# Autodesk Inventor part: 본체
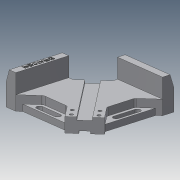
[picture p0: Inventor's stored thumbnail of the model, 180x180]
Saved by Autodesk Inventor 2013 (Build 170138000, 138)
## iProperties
Created: 2020-05
Part Number: 본체
Material: 알루미늄 6061
Document SubType Name: Modeling
Designer: user
Density: 2.71 g/cm^3
Mass: 582.584 g
Surface Area: 409.716 cm^2
Volume: 214.976 cm^3
Author: user
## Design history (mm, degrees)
sketch "스케치1"
  geometry: L1 (60, -60)-(-60, -60); L2 (-60, -60)-(-60, 60); L3 (-60, 60)-(60, 60); L4 (60, 60)-(60, -60); L5 (60, -60)-(-60, 60); L6 (-60, -60)-(60, 60); 1 further point
  constraints: 12 end point, 2 midpoint, 2 parallel, 1 horizontal, 1 perpendicular
  dimensions: "d0" = 120 distance of L2.end L3.end; "d1" = 120 distance of L1.end L2.end
extrude "돌출1" new body sketch "스케치1" distance "d2" = 18; taper "d3" = 0 deg
sketch "스케치2"
  geometry: L1 (-60, -60)-(60, -60) reference; L2 (60, -60)-(60, 60) reference; L3 (60, -60)-(80, -60); L4 (31.716, -60)-(60, -60); L5 (60, -31.716)-(60, -60); L6 (31.716, -60)-(60, -31.716); 1 further point
  constraints: 8 end point, 2 point on line, 1 collinear, 1 horizontal, 1 perpendicular
extrude "돌출2" cut sketch "스케치2" stored distance "d6" = 0; taper "d7" = 0 deg
sketch "스케치4"
  geometry: L1 (-60, 60)-(-10, 60); L2 (-10, 60)-(-10, 38.284); L3 (-38.284, 10)-(-60, 10); L4 (-60, 10)-(-60, 60); L5 (-38.284, 10)-(-10, 38.284); 1 further point
  constraints: 10 end point, 2 parallel, 1 horizontal, 1 perpendicular
extrude "돌출4" cut sketch "스케치4" distance "d16" = 18; taper "d17" = 0 deg
sketch "스케치3"
  geometry: L1 (0, 0)-(-40, 0) reference; L2 (-40, 18)-(0, 18) reference; L3 (-28, 18)-(-12, 18); L4 (-12, 18)-(-12, 14.5); L5 (-12, 14.5)-(-28, 14.5); L6 (-28, 14.5)-(-28, 18); L7 (-26, 3)-(-14, 3); L8 (-14, 3)-(-14, 0); L9 (-14, 0)-(-26, 0); L10 (-26, 0)-(-26, 3); 3 further points
  constraints: 16 end point, 4 midpoint, 4 parallel, 2 horizontal, 2 perpendicular
  dimensions: "d8" = 16 distance of L4.end L5.end; "d9" = 3.5 distance of L3.end L4.end; "d10" = 12 distance of L8.end L9.end; "d11" = 3 distance of L7.end L8.end
extrude "돌출3" cut sketch "스케치3" stored distance "d12" = 18; taper "d13" = 0 deg
sketch "스케치5"
  geometry: L1 (-60, -60)-(31.716, -60) reference; L2 (-60, 10)-(-45, 10); L3 (-45, 10)-(-45, -60); L4 (-45, -60)-(-60, -60); L5 (-60, -60)-(-60, 10); L6 (60, 60)-(-10, 60) reference; L7 (-10, 60)-(60, 60); L8 (60, 60)-(60, 45); L9 (60, 45)-(-10, 45); L10 (-10, 45)-(-10, 60); 1 further point
  constraints: 16 end point, 4 parallel, 2 horizontal, 2 perpendicular, 1 point on line
  dimensions: "d18" = 15 distance of L3.end L4.end; "d19" = 15 distance of L7.end L8.end
extrude "돌출5" join sketch "스케치5" distance "d20" = 24; taper "d21" = 0 deg
sketch "스케치7"
  geometry: L1 (-45, -60)-(31.716, -60) reference; L2 (31.716, -60)-(40.201, -51.515) reference; L3 (-38.284, 10)-(-45, 10) reference; L4 (-45, -60)-(-25, -40); L5 (-25, -40)-(11.716, -40); L6 (11.716, -40)-(31.716, -60); L7 (-60, 10)-(-60, -60) reference; 1 further point
  constraints: 6 end point, 4 point on line, 1 parallel, 1 perpendicular
  dimensions: "d37" = 20 distance between parallel lines of L1 L5; "d40" = 90 deg angle of L2 L6
extrude "돌출7" cut sketch "스케치7" stored distance "d41" = 24; taper "d42" = 0 deg
sketch "스케치8"
  geometry: L1 (45, 60)-(25, 40) reference; L2 (25, 40)-(-11.716, 40) reference; L3 (-11.716, 40)-(-31.716, 60) reference; L4 (40, 55)-(-26.716, 55); 1 further point
  constraints: 2 end point, 2 point on line
extrude "돌출8" join sketch "스케치8" distance "d44" = 8; taper "d45" = 0 deg
sketch "스케치9"
  geometry: L1 (-22, -44)-(6, -44); L2 (6, -44)-(6, -52); L3 (6, -52)-(-22, -52); L4 (-22, -52)-(-22, -44); L5 (-60, -60)-(-45, -60) reference; L6 (-60, 10)-(-60, -60) reference; C1 r 4 at (-22, -48); C2 r 4 at (6, -48); 1 further point
  constraints: 8 end point, 2 centre point, 2 midpoint, 2 parallel, 1 horizontal, 1 perpendicular
  dimensions: "d46" = 28 distance of L2.end L3.end; "d47" = 8 distance of L1.end L2.end; "d48" = 8 diameter of C1; "d49" = 8 diameter of C2; "d50" = 12 distance from line of L5 C1.centre; "d51" = 38 distance from line of L6 C1.centre
extrude "돌출9" cut sketch "스케치9" stored distance "d52" = 0; taper "d53" = 0 deg
node "작업 평면1"
sketch "스케치10"
  geometry: L1 (0, 0)-(15, 0) reference; L2 (0, -42)-(0, 0) reference; L3 (5, 0)-(0, -15); 1 further point
  constraints: 2 end point, 2 point on line
  dimensions: "d54" = 5 distance of L1.start L3.start; "d55" = 15 distance of L1.start L3.end
extrude "돌출10" cut sketch "스케치10" stored distance "d56" = 8; taper "d57" = 0 deg
sketch "스케치12"
  geometry: L1 (31.716, 60)-(26.716, 55) reference; L2 (41.615, 50.101)-(31.716, 60) reference; 3 further points
  dimensions: "d60" = 6 distance from line of L2 point (31.716, 51.515); "d61" = 18 distance from line of L2 point (23.23, 43.029); "d62" = 6 distance from line of L1 point (31.716, 51.515); "d63" = 6 distance from line of L1 point (23.23, 43.029)
hole "구멍1" sketch "스케치12" at (31.716, 51.515), (23.23, 43.029) diameter "d64" = 4.5; stored, may be unused: countersink angle "d68" = 90 deg, drill point angle "d70" = 118 deg; dims "d65" = 6, "d66" = 8, "d67" = 10, "d69" = 8
fillet "모깎기1" dims "d71" = 5
sketch "스케치14"
  geometry: L1 (-45, -60)-(-45, 10) reference; L2 (-45, 10)-(-55, 10) reference; L3 (-46.996, -5)-(-46.996, -46.479); L4 (-46.996, -46.479)-(-53, -46.479); L5 (-53, -46.479)-(-53, -5); L6 (-53, -5)-(-46.996, -5); 1 further point
  constraints: 2 other
  dimensions: "d74" = 15 distance between parallel lines of L2 L6; "d75" = 8 distance between parallel lines of L5 L1
feature "엠보싱1" sketch "스케치14" dims "d76" = 0.5, "d77" = 0
node "솔리드1"
mirror "대칭1"
mirror "대칭2"
mirror "대칭3"
